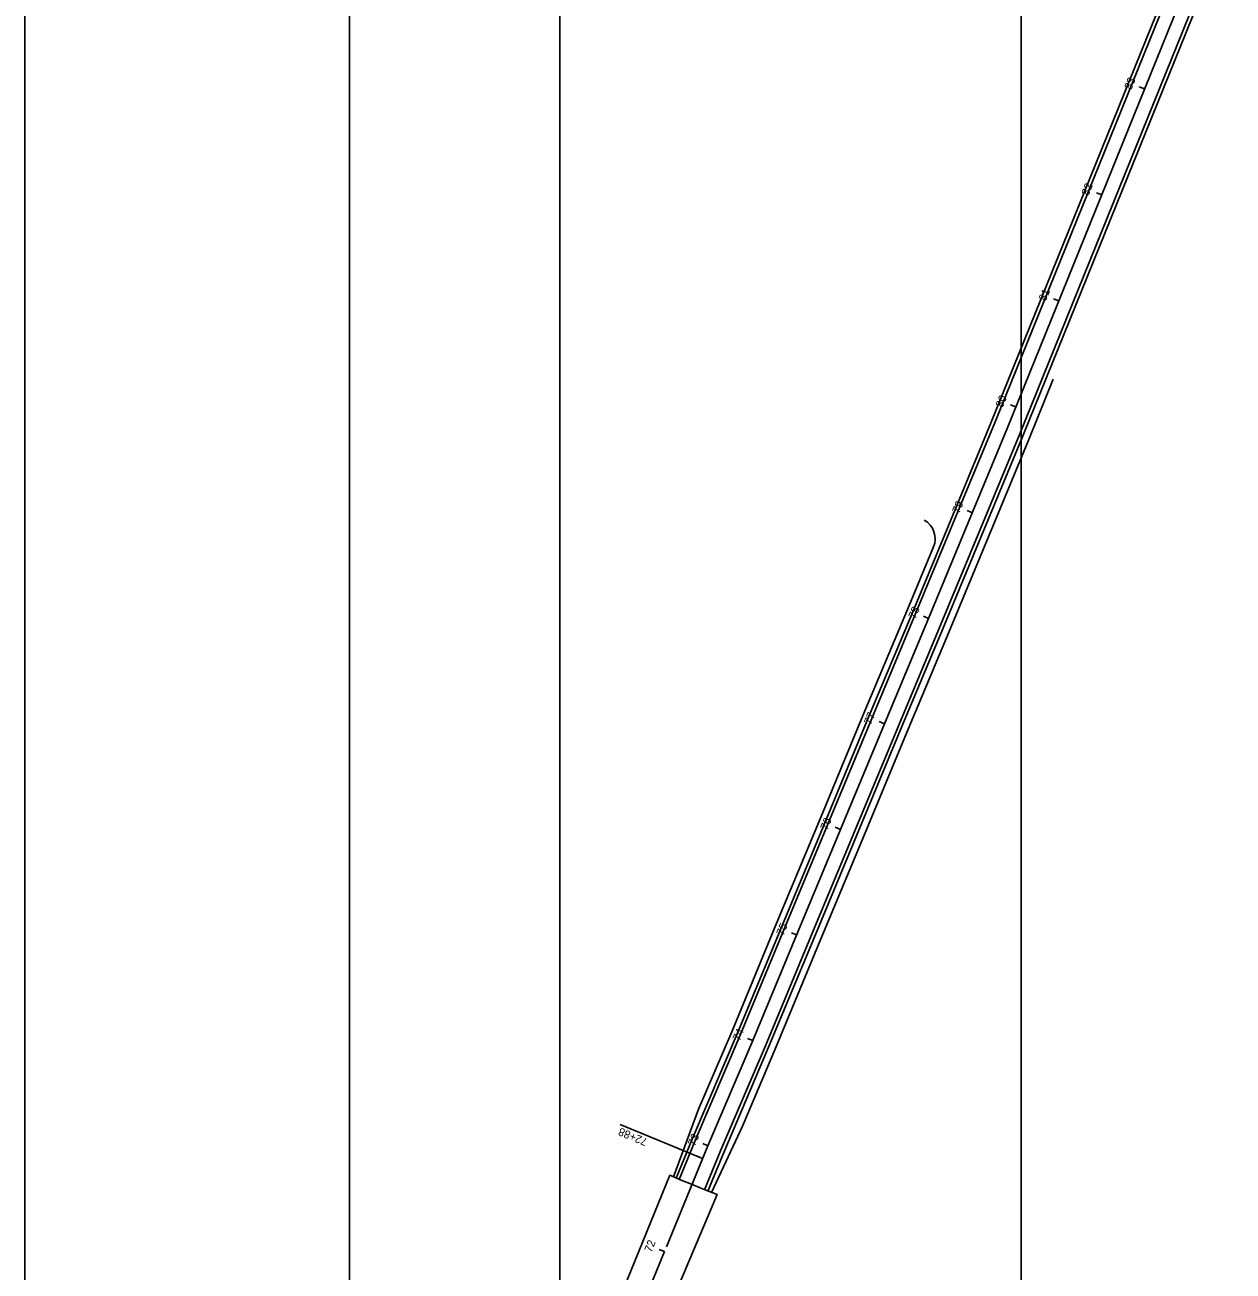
# Model space of a CAD drawing. Extents: x 2318076 to 2324211, y 613525 to 630327.
# Drawn here: x 2318413 to 2319469, y 622015 to 623105 of the extents above; entities that cross this region are included whole.
import ezdxf

# ---------------------------------------------------------------- set-up
doc = ezdxf.new("R2010")
doc.units = 0
for name, color, linetype in [('BR_X_Slab_Object', 7, 'Continuous'), ('GE_P_CL_50', 7, 'Continuous'), ('PV_P_EOP', 7, 'Continuous'), ('PV_P_Shoulder', 7, 'Continuous'), ('RD_X_GR_Lt', 7, 'Continuous'), ('RD_X_GR_Rt', 7, 'Continuous'), ('SC_Scratch3', 7, 'Continuous')]:
    doc.layers.add(name, color=color, linetype=linetype)

msp = doc.modelspace()

# ---------------------------------------------------------------- linework, layer by layer
at = {"layer": 'BR_X_Slab_Object'}
msp.add_lwpolyline([(2318975.9, 621982.3), (2318966.6, 621986.3), (2318955.8, 621991.1), (2318945.1, 621995.5), (2318936.1, 621999), (2318976.9, 622099.1), (2318986.6, 622094.8), (2318995.7, 622091.2), (2319006.8, 622086.5), (2319018.1, 622082.3), (2318975.9, 621982.3)], dxfattribs=at)
at = {"layer": 'GE_P_CL_50'}
for p, q in [((2319392, 623049.1), (2319387.3, 623050.9)), ((2319354.5, 622956.4), (2319349.8, 622958.3)), ((2319317, 622863.7), (2319312.3, 622865.6)), ((2319279.4, 622771), (2319274.8, 622772.9)), ((2319241.4, 622678.5), (2319236.8, 622680.4)), ((2319203.1, 622586.1), (2319198.5, 622588.1)), ((2319164.4, 622493.9), (2319159.8, 622495.8)), ((2319126.1, 622401.5), (2319121.5, 622403.5)), ((2319087.7, 622309.2), (2319083.1, 622311.1)), ((2319049.4, 622216.8), (2319044.8, 622218.8)), ((2319005.5, 622113.8), (2318933.4, 622143.4)), ((2319010.1, 622124.9), (2319005.6, 622126.8)), ((2319005.4, 622113.8), (2319000.8, 622115.8)), ((2318972.2, 622032.3), (2318967.6, 622034.2))]:
    msp.add_line(p, q, dxfattribs=at)
for points in [[(2318973.8, 622036.6), (2319010.1, 622124.9), (2319049.4, 622216.8), (2319089, 622312.5), (2319126.1, 622401.5), (2319164.4, 622493.9), (2319203.1, 622586.1), (2319241.6, 622679), (2319271.8, 622752.1), (2319455.4, 623205.9)], [(2318934.1, 621939.9), (2318972.1, 622032.4)]]:
    msp.add_lwpolyline(points, dxfattribs=at)
at = {"layer": 'PV_P_EOP'}
for points in [[(2318985, 622095.4), (2318999, 622129.5), (2319038.3, 622221.5), (2319077.9, 622317.1), (2319115, 622406.2), (2319153.3, 622498.5), (2319192, 622590.8), (2319230.5, 622683.5), (2319260.7, 622756.6), (2319444.3, 623210.4)], [(2319007.2, 622086.4), (2319021.1, 622120.3), (2319060.4, 622212.2), (2319100.1, 622307.9), (2319137.2, 622396.9), (2319175.5, 622489.3), (2319214.2, 622581.5), (2319252.7, 622674.4), (2319282.9, 622747.5), (2319466.6, 623201.5)]]:
    msp.add_lwpolyline(points, dxfattribs=at)
at = {"layer": 'PV_P_Shoulder'}
for points in [[(2318982.2, 622096.6), (2318996.2, 622130.7), (2319035.6, 622222.7), (2319075.2, 622318.2), (2319112.2, 622407.3), (2319150.5, 622499.7), (2319189.2, 622591.9), (2319227.7, 622684.7), (2319257.9, 622757.8), (2319441.5, 623211.5)], [(2319010, 622085.2), (2319023.9, 622119.1), (2319063.2, 622211), (2319102.9, 622306.7), (2319139.9, 622395.8), (2319178.2, 622488.1), (2319216.9, 622580.4), (2319255.5, 622673.2), (2319285.7, 622746.4), (2319469.4, 623200.3)]]:
    msp.add_lwpolyline(points, dxfattribs=at)
at = {"layer": 'RD_X_GR_Lt'}
msp.add_line((2318980.1, 622097.7), (2319002, 622156.8), dxfattribs=at)
msp.add_lwpolyline([(2319002, 622156.8), (2319031, 622224.6), (2319070.5, 622320.2), (2319107.6, 622409.2), (2319145.9, 622501.6), (2319184.6, 622593.8), (2319207.4, 622648.6)], dxfattribs=at)
msp.add_arc((2319190.1, 622655.8), 18.7, 337.427, 60.4986, dxfattribs=at)
at = {"layer": 'RD_X_GR_Rt'}
msp.add_line((2319013.3, 622084.1), (2319040.3, 622142.1), dxfattribs=at)
msp.add_lwpolyline([(2319040.3, 622142.1), (2319068.7, 622208.7), (2319108.4, 622304.4), (2319145.5, 622393.5), (2319183.8, 622485.8), (2319222.5, 622578), (2319261, 622670.9), (2319291.2, 622744.1), (2319311.9, 622795.3)], dxfattribs=at)
at = {"layer": 'SC_Scratch3'}
for p, q in [((2318412.8, 614778.4), (2318412.8, 630327.2)), ((2318696.7, 614778.4), (2318696.7, 630327.2)), ((2318880.5, 614778.4), (2318880.5, 630327.2)), ((2319283.9, 614778.4), (2319283.9, 630327.2))]:
    msp.add_line(p, q, dxfattribs=at)

# ---------------------------------------------------------------- texts
at = {"layer": 'GE_P_CL_50'}
for s, rotation, p in [('83', 68.3971, (2319380.4, 623047.8)), ('82', 67.8067, (2319342.9, 622955.2)), ('81', 67.3882, (2319305.5, 622862.9)), ('80', 67.3882, (2319267.8, 622769.8)), ('79', 67.4813, (2319229.8, 622677.3)), ('78', 67.1236, (2319191.5, 622585)), ('77', 67.5842, (2319152.7, 622492.5)), ('76', 67.4396, (2319114.5, 622400.3)), ('75', 67.6176, (2319076.1, 622308.1)), ('74', 67.024, (2319037.8, 622215.9)), ('72+88', 157.6281, (2318957.9, 622130.9)), ('73', 66.7314, (2318998.6, 622124)), ('72', 68.2796, (2318960.7, 622031.1))]:
    msp.add_text(s, height=7, rotation=rotation, dxfattribs=at).set_placement(p)

doc.saveas('drawing.dxf')
